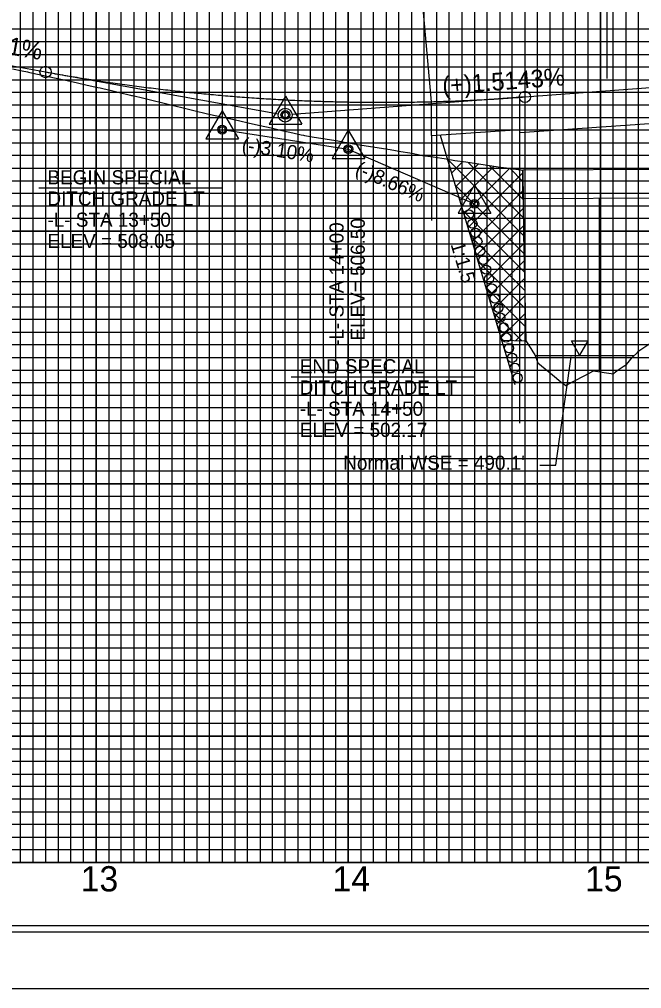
# Model space of a CAD drawing. Extents: x 573715 to 575626, y -55474 to -54374.
# Drawn here: x 574251.9 to 574498.5, y -55474.4 to -55090.5 of the extents above; entities that cross this region are included whole.
import ezdxf

# ---------------------------------------------------------------- set-up
doc = ezdxf.new("R2010")
doc.units = 0
for name, color, linetype in [('Default', 7, 'Continuous'), ('Exist Profile Cell', 7, 'Continuous'), ('Exist Vertical Profile Ground Line', 7, 'Continuous'), ('Exist Vertical Profile Horizontal Axis Label Major', 7, 'Continuous'), ('Prop PFL Text', 7, 'Continuous'), ('Prop PFL VPI Symbol CELL', 7, 'Continuous'), ('Prop Roadway Bridge', 7, 'Continuous'), ('Prop Vertical Profile Curve Label', 7, 'Continuous'), ('Prop Vertical Profile Ditch Grade Left', 7, 'Continuous'), ('Prop Vertical Profile Ditch Grade Left Label', 7, 'Continuous'), ('Prop Vertical Profile Grade', 7, 'Continuous'), ('Prop Vertical Profile Grade Label', 7, 'Continuous'), ('Prop VPI Label', 7, 'Continuous'), ('Sheet Cutting Line CELL', 7, 'Continuous'), ('Sheet DOT Grid CELL', 7, 'Continuous'), ('Sheet Layout Profile Border', 7, 'Continuous'), ('Sheet Plot Border Inside CELL', 7, 'Continuous'), ('Sheet Plot Border Outside CELL', 7, 'Continuous'), ('Sheet Profile CELL', 7, 'Continuous'), ('Sheet Profile Grid Major CELL', 7, 'Continuous'), ('Sheet Profile Grid Middle CELL', 7, 'Continuous'), ('Sheet Profile Grid Minor CELL', 7, 'Continuous')]:
    doc.layers.add(name, color=color, linetype=linetype)

msp = doc.modelspace()

# ---------------------------------------------------------------- linework, layer by layer
at = {"layer": 'Default'}
for p, q in [((574451.39, -55150.07), (574542.22, -55149.62)), ((574451.39, -55161.42), (574451.39, -55150.07)), ((574451.39, -55161.42), (574542.22, -55161.07)), ((574481.89, -55230.07), (574481.89, -55161.3)), ((574481.89, -55230.07), (574481.89, -55161.3))]:
    msp.add_line(p, q, dxfattribs=at)
at = {"layer": 'Exist Profile Cell'}
msp.add_line((573982.27, -55224.42), (575001.21, -55224.42), dxfattribs=at)
at = {"layer": 'Exist Vertical Profile Ground Line'}
msp.add_lwpolyline([(574249.19, -55110.07), (574252.97, -55110.89), (574255.08, -55111.34), (574255.49, -55111.43), (574257.26, -55111.81), (574261.55, -55112.75), (574265.84, -55113.69), (574270.13, -55114.63), (574274.42, -55115.58), (574278.71, -55116.53), (574283, -55117.49), (574283.87, -55117.68), (574285.46, -55118.03), (574287.29, -55118.46), (574291.58, -55119.48), (574295.87, -55120.51), (574296.38, -55120.63), (574296.77, -55120.72), (574297.86, -55120.97), (574300.15, -55121.52), (574304.44, -55122.56), (574308.73, -55123.6), (574313.02, -55124.64), (574317.31, -55125.69), (574321.6, -55126.74), (574325.89, -55127.8), (574326.95, -55128.05), (574330.18, -55128.75), (574334.47, -55129.68), (574335.1, -55129.81), (574336.93, -55130.22), (574338.76, -55130.62), (574343.05, -55131.59), (574347.34, -55132.55), (574351.63, -55133.51), (574355.92, -55134.48), (574360.21, -55135.44), (574363.61, -55136.22), (574364.5, -55136.44), (574364.95, -55136.55), (574368.78, -55137.17), (574373.07, -55137.86), (574377.36, -55138.55), (574379.59, -55138.91), (574381.12, -55139.22), (574381.65, -55139.31), (574385.94, -55140.01), (574390.23, -55140.71), (574394.52, -55141.41), (574398.81, -55142.11), (574403.1, -55142.82), (574406.59, -55143.39), (574407.39, -55143.55), (574411.13, -55144.31), (574411.68, -55144.38), (574415.97, -55145.01), (574419.4, -55145.51), (574420.26, -55145.66), (574423.19, -55146.17), (574424.55, -55146.37), (574428.84, -55147), (574433.13, -55147.63), (574437.41, -55148.25), (574441.7, -55148.88), (574445.99, -55149.51), (574446.76, -55149.62), (574449.56, -55150), (574450.28, -55150.04), (574451.45, -55150.31), (574451.65, -55175.62), (574452.64, -55217.82), (574454.57, -55220.91), (574455.36, -55222.17), (574456.23, -55223.37), (574457.4, -55226.55), (574458.86, -55227.76), (574463.15, -55231.32), (574466.51, -55234.11), (574467.44, -55234.73), (574468.52, -55235.47), (574471.73, -55233.78), (574476.02, -55231.53), (574479.49, -55229.72), (574480.31, -55229.84), (574484.6, -55230.46), (574487.46, -55230.87), (574487.99, -55230.21), (574488.89, -55229.61), (574491.22, -55228.06), (574492.57, -55227.19), (574493.18, -55226.45), (574494.78, -55224.49), (574496.97, -55222.41), (574497.4, -55221.8), (574501.76, -55218.83)], dxfattribs=at)
at = {"layer": 'Prop PFL Text'}
for p, q in [((574421.53, -55145.93), (574451.66, -55176.06)), ((574423.16, -55151.37), (574427.69, -55146.83)), ((574424.79, -55156.81), (574433.86, -55147.73)), ((574429.81, -55147.14), (574451.6, -55168.93)), ((574426.42, -55162.25), (574440.03, -55148.64)), ((574428.05, -55167.69), (574446.2, -55149.54)), ((574429.69, -55173.13), (574451.45, -55151.36)), ((574438.09, -55148.35), (574451.54, -55161.8)), ((574446.37, -55149.56), (574451.48, -55154.67)), ((574424.56, -55156.03), (574451.83, -55183.31)), ((574431.32, -55178.57), (574451.51, -55158.37)), ((574427.59, -55166.13), (574452, -55190.55)), ((574432.95, -55184), (574451.57, -55165.39)), ((574434.58, -55189.44), (574451.63, -55172.4)), ((574430.62, -55176.23), (574452.17, -55197.79)), ((574436.21, -55194.88), (574451.74, -55179.36)), ((574433.65, -55186.34), (574452.34, -55205.03)), ((574437.84, -55200.32), (574451.9, -55186.27)), ((574439.48, -55205.76), (574452.06, -55193.18)), ((574436.68, -55196.44), (574452.51, -55212.27)), ((574441.11, -55211.2), (574452.22, -55200.08)), ((574439.71, -55206.54), (574450.95, -55217.77)), ((574442.74, -55216.64), (574452.39, -55206.99)), ((574442.74, -55216.64), (574443.69, -55217.59)), ((574448.73, -55217.72), (574452.55, -55213.9))]:
    msp.add_line(p, q, dxfattribs=at)
at = {"layer": 'Prop PFL VPI Symbol CELL'}
for p, q in [((574357.32, -55120.87), (574350.87, -55132.07)), ((574357.32, -55120.87), (574363.82, -55132.07)), ((574332.27, -55126.69), (574325.82, -55137.89)), ((574332.27, -55126.69), (574338.77, -55137.89)), ((574350.87, -55132.07), (574363.82, -55132.07)), ((574382.27, -55134.44), (574375.82, -55145.64)), ((574382.27, -55134.44), (574388.77, -55145.64)), ((574325.82, -55137.89), (574338.77, -55137.89)), ((574375.82, -55145.64), (574388.77, -55145.64)), ((574432.27, -55156.09), (574425.82, -55167.29)), ((574432.27, -55156.09), (574438.77, -55167.29)), ((574425.82, -55167.29), (574438.77, -55167.29))]:
    msp.add_line(p, q, dxfattribs=at)
for centre, radius in [((574357.33, -55128.35), 1.75), ((574357.33, -55128.35), 1.2), ((574332.27, -55134.17), 1.75), ((574332.27, -55134.17), 1.2), ((574382.27, -55141.92), 1.75), ((574382.27, -55141.92), 1.2), ((574432.27, -55163.57), 1.75), ((574432.27, -55163.57), 1.2)]:
    msp.add_circle(centre, radius, dxfattribs=at)
at = {"layer": 'Prop Roadway Bridge'}
for p, q in [((574415.29, -55136.57), (574415.29, -55123.11)), ((574450.29, -55134.12), (574450.29, -55121.38)), ((574450.29, -55135.37), (574520.29, -55130.47)), ((574415.29, -55136.57), (574450.29, -55134.12)), ((574415.29, -55136.57), (574415.29, -55170.14)), ((574418.65, -55136.33), (574448.27, -55235.08)), ((574450.29, -55250.46), (574450.29, -55134.12)), ((574443.02, -55217.58), (574452.64, -55217.82)), ((574473.94, -55223.48), (574470.69, -55217.88)), ((574470.69, -55217.88), (574477.16, -55217.88)), ((574477.16, -55217.88), (574473.94, -55223.48)), ((574456.32, -55223.6), (574495.72, -55223.6)), ((574464.57, -55267.14), (574470.64, -55224.17)), ((574458.17, -55267.14), (574464.57, -55267.14))]:
    msp.add_line(p, q, dxfattribs=at)
for centre in [(574430.1, -55167.72), (574431.46, -55171.44), (574432.7, -55175.03), (574433.44, -55178.5), (574434.56, -55182.22), (574435.79, -55185.81), (574436.91, -55189.65), (574438.02, -55193.37), (574439.14, -55197.09), (574440.38, -55201.05), (574441.74, -55204.77), (574442.48, -55208.61), (574443.84, -55212.57), (574444.84, -55216.54), (574445.95, -55220.75), (574447.19, -55224.59), (574448.3, -55228.56), (574449.42, -55232.52)]:
    msp.add_circle(centre, 1.83, dxfattribs=at)
at = {"layer": 'Prop Vertical Profile Curve Label'}
for centre in [(574262.27, -55111.35), (574452.27, -55121.23)]:
    msp.add_circle(centre, 2.25, dxfattribs=at)
at = {"layer": 'Prop Vertical Profile Ditch Grade Left'}
msp.add_lwpolyline([(574332.27, -55134.17), (574382.27, -55141.92), (574432.27, -55163.57)], dxfattribs=at)
at = {"layer": 'Prop Vertical Profile Ditch Grade Left Label'}
for p, q in [((574332.27, -55134.17), (574332.27, -55157.28)), ((574382.27, -55141.92), (574382.27, -55221.36)), ((574259.62, -55157.28), (574332.27, -55157.28)), ((574432.27, -55163.57), (574432.27, -55232.12)), ((574359.62, -55232.12), (574432.27, -55232.12))]:
    msp.add_line(p, q, dxfattribs=at)
at = {"layer": 'Prop Vertical Profile Grade'}
for p, q in [((574212.27, -55102.37), (574262.27, -55111.35)), ((574452.27, -55121.23), (574542.27, -55114.41))]:
    msp.add_line(p, q, dxfattribs=at)
msp.add_spline([(574262.27, -55111.35), (574266.07, -55112.03), (574269.87, -55112.68), (574273.67, -55113.31), (574277.47, -55113.93), (574281.27, -55114.52), (574285.07, -55115.1), (574288.87, -55115.66), (574292.67, -55116.19), (574296.47, -55116.71), (574300.27, -55117.21), (574304.07, -55117.69), (574307.87, -55118.15), (574311.67, -55118.59), (574315.47, -55119.01), (574319.27, -55119.41), (574323.07, -55119.79), (574326.87, -55120.15), (574330.67, -55120.5), (574334.47, -55120.82), (574338.27, -55121.13), (574342.07, -55121.41), (574345.87, -55121.68), (574349.67, -55121.92), (574353.47, -55122.15), (574357.27, -55122.36), (574361.07, -55122.54), (574364.87, -55122.71), (574368.67, -55122.86), (574372.47, -55122.99), (574376.27, -55123.1), (574380.07, -55123.19), (574383.87, -55123.26), (574387.67, -55123.31), (574391.47, -55123.35), (574395.27, -55123.36), (574399.07, -55123.35), (574402.87, -55123.33), (574406.67, -55123.28), (574410.47, -55123.22), (574414.27, -55123.13), (574418.07, -55123.03), (574421.87, -55122.91), (574425.67, -55122.77), (574429.47, -55122.6), (574433.27, -55122.42), (574437.07, -55122.22), (574440.87, -55122), (574444.67, -55121.76), (574448.47, -55121.51), (574452.27, -55121.23)], degree=3, dxfattribs=at)
at = {"layer": 'Prop VPI Label'}
for p, q in [((574484.77, -54944.13), (574484.77, -55113.91)), ((574415.29, -55123.11), (574400.89, -54963.98)), ((574262.27, -55111.35), (574354.57, -55127.93)), ((574452.27, -55121.23), (574360.02, -55128.21))]:
    msp.add_line(p, q, dxfattribs=at)
msp.add_circle((574357.27, -55128.42), 2.75, dxfattribs=at)
at = {"layer": 'Sheet Cutting Line CELL'}
msp.add_line((573715.27, -55474.42), (575399.27, -55474.42), dxfattribs=at)
at = {"layer": 'Sheet DOT Grid CELL'}
for p, q in [((574282.27, -54399.42), (574282.27, -55424.42)), ((574332.27, -54399.42), (574332.27, -55424.42)), ((574382.27, -54399.42), (574382.27, -55424.42)), ((574432.27, -54399.42), (574432.27, -55424.42)), ((574482.27, -54399.42), (574482.27, -55424.42)), ((573882.27, -55124.42), (575382.27, -55124.42)), ((573882.27, -55174.42), (575382.27, -55174.42)), ((573882.27, -55224.42), (575382.27, -55224.42)), ((573882.27, -55274.42), (575382.27, -55274.42)), ((573882.27, -55324.42), (575382.27, -55324.42)), ((573882.27, -55374.42), (575382.27, -55374.42))]:
    msp.add_line(p, q, dxfattribs=at)
at = {"layer": 'Sheet Layout Profile Border'}
msp.add_lwpolyline([(573932.27, -54399.42), (573932.27, -55424.42), (575332.27, -55424.42), (575332.27, -54536.97), (575182.22, -54536.97), (575182.22, -54399.42)], close=True, dxfattribs=at)
at = {"layer": 'Sheet Plot Border Inside CELL'}
msp.add_lwpolyline([(575394.77, -54396.87), (573728.27, -54396.87), (573728.27, -55451.97), (575394.77, -55451.97)], close=True, dxfattribs=at)
msp.add_lwpolyline([(575394.77, -54396.87), (573728.27, -54396.87), (573728.27, -55451.97), (575394.77, -55451.97)], close=True, dxfattribs=at)
at = {"layer": 'Sheet Plot Border Outside CELL'}
msp.add_lwpolyline([(575399.27, -54374.42), (573715.27, -54374.42), (573715.27, -55474.42), (575399.27, -55474.42)], close=True, dxfattribs=at)
at = {"layer": 'Sheet Profile CELL'}
msp.add_line((575382.27, -55424.42), (573882.27, -55424.42), dxfattribs=at)
msp.add_lwpolyline([(575382.27, -54399.42), (573882.27, -54399.42), (573882.27, -55449.42), (575382.27, -55449.42)], close=True, dxfattribs=at)
at = {"layer": 'Sheet Profile Grid Major CELL'}
for points in [[(574232.27, -55424.42), (574282.27, -55424.42), (574282.27, -54399.42)], [(574332.27, -54399.42), (574332.27, -55424.42), (574382.27, -55424.42), (574382.27, -54399.42)], [(574432.27, -54399.42), (574432.27, -55424.42), (574482.27, -55424.42), (574482.27, -54399.42)], [(575382.27, -55174.42), (573882.27, -55174.42), (573882.27, -55124.42), (575382.27, -55124.42)], [(575382.27, -55274.42), (573882.27, -55274.42), (573882.27, -55224.42), (575382.27, -55224.42)], [(575382.27, -55374.42), (573882.27, -55374.42), (573882.27, -55324.42), (575382.27, -55324.42)]]:
    msp.add_lwpolyline(points, dxfattribs=at)
at = {"layer": 'Sheet Profile Grid Middle CELL'}
for points in [[(574207.27, -55424.42), (574257.27, -55424.42), (574257.27, -54399.42)], [(574307.27, -54399.42), (574307.27, -55424.42), (574357.27, -55424.42), (574357.27, -54399.42)], [(574407.27, -54399.42), (574407.27, -55424.42), (574457.27, -55424.42), (574457.27, -54399.42)], [(575382.27, -55099.42), (573882.27, -55099.42), (573882.27, -55149.42), (575382.27, -55149.42)], [(575382.27, -55199.42), (573882.27, -55199.42), (573882.27, -55249.42), (575382.27, -55249.42)], [(575382.27, -55299.42), (573882.27, -55299.42), (573882.27, -55349.42), (575382.27, -55349.42)], [(575382.27, -55399.42), (573882.27, -55399.42)]]:
    msp.add_lwpolyline(points, dxfattribs=at)
at = {"layer": 'Sheet Profile Grid Minor CELL'}
for points in [[(574247.27, -55424.42), (574252.27, -55424.42), (574252.27, -54399.42)], [(574262.27, -54399.42), (574262.27, -55424.42), (574277.27, -55424.42), (574277.27, -54399.42)], [(574267.27, -54399.42), (574267.27, -55424.42), (574272.27, -55424.42), (574272.27, -54399.42)], [(574287.27, -54399.42), (574287.27, -55424.42), (574292.27, -55424.42), (574292.27, -54399.42)], [(574297.27, -54399.42), (574297.27, -55424.42), (574302.27, -55424.42), (574302.27, -54399.42)], [(574312.27, -54399.42), (574312.27, -55424.42), (574317.27, -55424.42), (574317.27, -54399.42)], [(574322.27, -54399.42), (574322.27, -55424.42), (574327.27, -55424.42), (574327.27, -54399.42)], [(574337.27, -54399.42), (574337.27, -55424.42), (574342.27, -55424.42), (574342.27, -54399.42)], [(574347.27, -54399.42), (574347.27, -55424.42), (574352.27, -55424.42), (574352.27, -54399.42)], [(574362.27, -54399.42), (574362.27, -55424.42), (574367.27, -55424.42), (574367.27, -54399.42)], [(574372.27, -54399.42), (574372.27, -55424.42), (574377.27, -55424.42), (574377.27, -54399.42)], [(574387.27, -54399.42), (574387.27, -55424.42), (574392.27, -55424.42), (574392.27, -54399.42)], [(574397.27, -54399.42), (574397.27, -55424.42), (574402.27, -55424.42), (574402.27, -54399.42)], [(574412.27, -54399.42), (574412.27, -55424.42)], [(574417.27, -54399.42), (574417.27, -55424.42), (574422.27, -55424.42), (574422.27, -54399.42), (574427.27, -54399.42), (574427.27, -55424.42), (574437.27, -55424.42), (574437.27, -54399.42), (574442.27, -54399.42), (574442.27, -55424.42), (574447.27, -55424.42), (574447.27, -54399.42), (574452.27, -54399.42), (574452.27, -55424.42)], [(574462.27, -55424.42), (574462.27, -54399.42)], [(574467.27, -54399.42), (574467.27, -55424.42), (574472.27, -55424.42), (574472.27, -54399.42)], [(574477.27, -54399.42), (574477.27, -55424.42), (574487.27, -55424.42), (574487.27, -54399.42)], [(574492.27, -54399.42), (574492.27, -55424.42), (574492.27, -55424.42), (574497.27, -55424.42), (574497.27, -54399.42)], [(574267.27, -54400.02), (574267.27, -55424.42), (574272.27, -55424.42), (574272.27, -54400.02)], [(575332.27, -55094.42), (573932.27, -55094.42), (573932.27, -55104.42), (575332.27, -55104.42)], [(575332.27, -55109.42), (573932.27, -55109.42), (573932.27, -55114.42), (575332.27, -55114.42)], [(575332.27, -55119.42), (573932.27, -55119.42), (573932.27, -55129.42), (575332.27, -55129.42)], [(575332.27, -55134.42), (573932.27, -55134.42), (573932.27, -55139.42), (575332.27, -55139.42)], [(575332.27, -55144.42), (573932.27, -55144.42), (573932.27, -55154.42), (575332.27, -55154.42)], [(575332.27, -55159.42), (573932.27, -55159.42), (573932.27, -55164.42), (575332.27, -55164.42)], [(575332.27, -55169.42), (573932.27, -55169.42), (573932.27, -55179.42), (575332.27, -55179.42)], [(575332.27, -55184.42), (573932.27, -55184.42), (573932.27, -55189.42), (575332.27, -55189.42)], [(575332.27, -55194.42), (573932.27, -55194.42), (573932.27, -55204.42), (575332.27, -55204.42)], [(575332.27, -55209.42), (573932.27, -55209.42), (573932.27, -55214.42), (575332.27, -55214.42)], [(575332.27, -55219.42), (573932.27, -55219.42)], [(573932.27, -55229.42), (575332.27, -55229.42)], [(575332.27, -55234.42), (573932.27, -55234.42), (573932.27, -55239.42), (575332.27, -55239.42)], [(575332.27, -55244.42), (573932.27, -55244.42)], [(573932.27, -55254.42), (575332.27, -55254.42)], [(575332.27, -55259.42), (573932.27, -55259.42), (573932.27, -55264.42), (575332.27, -55264.42)], [(575332.27, -55269.42), (573932.27, -55269.42), (573932.27, -55279.42), (575332.27, -55279.42)], [(575332.27, -55284.42), (573932.27, -55284.42), (573932.27, -55289.42), (575332.27, -55289.42)], [(575332.27, -55294.42), (573932.27, -55294.42), (573932.27, -55304.42), (575332.27, -55304.42)], [(575332.27, -55309.42), (573932.27, -55309.42), (573932.27, -55314.42), (575332.27, -55314.42)], [(575332.27, -55319.42), (573932.27, -55319.42), (573932.27, -55329.42), (575332.27, -55329.42)], [(575332.27, -55334.42), (573932.27, -55334.42), (573932.27, -55339.42), (575332.27, -55339.42)], [(575332.27, -55344.42), (573932.27, -55344.42), (573932.27, -55354.42), (575332.27, -55354.42)], [(575332.27, -55359.42), (573932.27, -55359.42), (573932.27, -55364.42), (575332.27, -55364.42)], [(575332.27, -55369.42), (573932.27, -55369.42), (573932.27, -55379.42), (575332.27, -55379.42)], [(575332.27, -55384.42), (573932.27, -55384.42), (573932.27, -55389.42), (575332.27, -55389.42)], [(575332.27, -55394.42), (573932.27, -55394.42), (573932.27, -55404.42), (575332.27, -55404.42)], [(575332.27, -55409.42), (573932.27, -55409.42), (573932.27, -55414.42), (575332.27, -55414.42)], [(575332.27, -55419.42), (573932.27, -55419.42)]]:
    msp.add_lwpolyline(points, dxfattribs=at)

# ---------------------------------------------------------------- texts
at = {"layer": 'Exist Vertical Profile Horizontal Axis Label Major'}
for s, p in [('13', (574276.18, -55435.92)), ('14', (574376.03, -55435.92)), ('15', (574476.12, -55435.92))]:
    msp.add_text(s, height=10, dxfattribs=at).set_placement(p)
at = {"layer": 'Prop Roadway Bridge'}
msp.add_text('1:1.5', height=5.6, rotation=286.6992, dxfattribs=at).set_placement((574422.75, -55179.57))
at = {"layer": 'Prop Vertical Profile Curve Label'}
msp.add_text("Normal WSE = 490.1'", height=5.6, dxfattribs=at).set_placement((574380.27, -55268.93))
at = {"layer": 'Prop Vertical Profile Ditch Grade Left'}
for s, rotation, p in [('(-)3.10%', 351.1893, (574339.78, -55142.79)), ('(-)8.66%', 336.5874, (574384.57, -55151.65))]:
    msp.add_text(s, height=5.6, rotation=rotation, dxfattribs=at).set_placement(p)
at = {"layer": 'Prop Vertical Profile Ditch Grade Left Label'}
for s, p in [('BEGIN SPECIAL', (574263.01, -55155.86)), ('DITCH GRADE LT', (574263.01, -55164.26)), ('-L- STA 13+50', (574263.01, -55172.66)), ('ELEV = 508.05', (574263.01, -55181.06)), ('END SPECIAL', (574363.01, -55230.71)), ('DITCH GRADE LT', (574363.01, -55239.11)), ('-L- STA 14+50', (574363.01, -55247.51)), ('ELEV = 502.17', (574363.01, -55255.91))]:
    msp.add_text(s, height=5.6, dxfattribs=at).set_placement(p)
for s, p in [(' ELEV= 506.50', (574388.8, -55219.82)), ('-L- STA 14+00', (574380.4, -55219.82))]:
    msp.add_text(s, height=5.6, rotation=90, dxfattribs=at).set_placement(p)
at = {"layer": 'Prop Vertical Profile Grade Label'}
for s, rotation, p in [('(-)3.5931%', 349.8152, (574214.75, -55098.46)), ('(+)1.5143%', 4.3298, (574419.78, -55120.28))]:
    msp.add_text(s, height=7, rotation=rotation, dxfattribs=at).set_placement(p)

doc.saveas('drawing.dxf')
